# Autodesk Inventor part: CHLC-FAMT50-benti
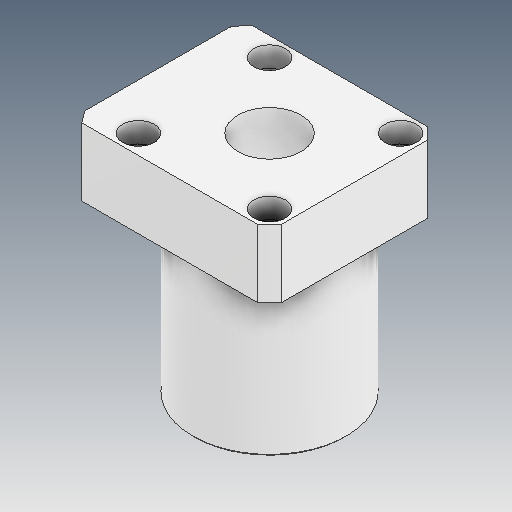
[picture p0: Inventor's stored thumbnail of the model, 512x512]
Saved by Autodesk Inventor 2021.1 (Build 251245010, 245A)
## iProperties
Created: 2021-05
Part Number: CHLC-FAMT50-benti
Material: Ogólny
Document SubType Name: Modeling
Designer: user
Density: 1 g/cm^3
Appearance: Domyślna
Author: user
Revision Number: ÈÎºÎ
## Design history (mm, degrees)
feature "µ¹½Ç1"
node "Bryła1"
